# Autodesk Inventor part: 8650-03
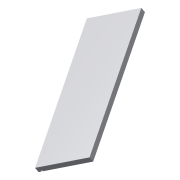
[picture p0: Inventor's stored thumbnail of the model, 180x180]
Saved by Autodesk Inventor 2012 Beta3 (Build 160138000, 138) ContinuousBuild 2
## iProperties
Created: 2011-02
Part Number: 8650-03
Material: Default
Document SubType Name: Modeling
Designer: Beta-8540w
Density: 1 g/cm^3
Author: Beta-8540w
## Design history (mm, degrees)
derived "c15-13.ipt" dims "d2" = 12.7, "d3" = 0, "d4" = 6.35, "d6" = 3.302, "d7" = 0, "drawer_depth" = 361.95, "drawer_side_height" = 127, "bottom_thickness" = 3.302
body "Solid1"
feature "Solid1::c15-13.ipt" dims "d2" = 12.7, "d3" = 0, "d4" = 6.35, "d6" = 3.302, "d7" = 0, "drawer_depth" = 361.95, "drawer_side_height" = 127, "bottom_thickness" = 3.302, "ScaleForDerivedMember" = 10
tag "TaggingFeature1"
